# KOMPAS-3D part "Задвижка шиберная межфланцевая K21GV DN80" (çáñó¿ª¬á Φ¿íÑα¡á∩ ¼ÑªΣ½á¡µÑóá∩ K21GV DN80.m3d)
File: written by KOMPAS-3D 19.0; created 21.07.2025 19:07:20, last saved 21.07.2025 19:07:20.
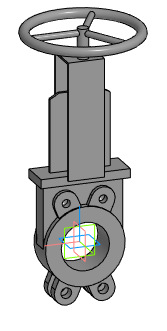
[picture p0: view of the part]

Document properties: Автор: Евгений; Полное имя файла: E:\Dendor Работа Сачек\3D для проектировщиков\2.3 Тип K21GV. Задвижка шиберная межфланцевая\stp_Задвижка шиберная K21GV DN50-400 с маховиком\Задвижка шиберная межфланцевая K21GV DN80.m3d

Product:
- Part/product: Задвижка шиберная межфланцевая K21GV DN80

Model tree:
1. Операция без истории:1  (labels: Задвижка шиберная межфланцевая K21GV DN80)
